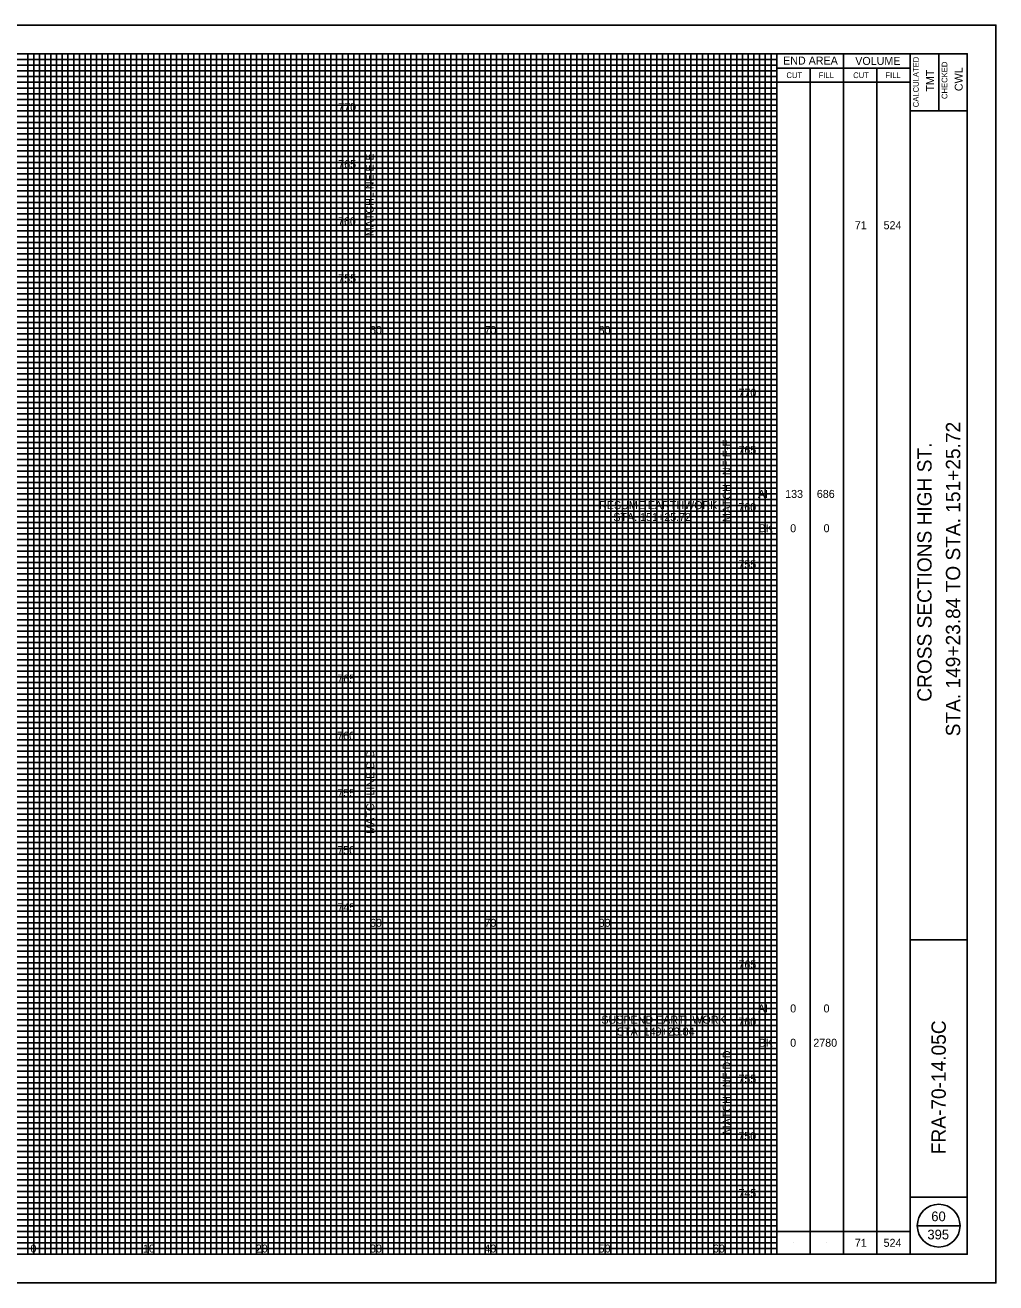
# Model space of a CAD drawing. Extents: x -10 to 160, y -2 to 568.
# Drawn here: x 75.1 to 160, y 227.5 to 337.5 of the extents above; entities that cross this region are included whole.
import ezdxf

# ---------------------------------------------------------------- set-up
doc = ezdxf.new("R2010")
doc.units = 0
for name, color, linetype in [('DR_P_Text', 7, 'Continuous'), ('SV_X_Text_Comment', 7, 'Continuous'), ('SV_X_Text_Elevation', 7, 'Continuous'), ('XS_P_Annotation', 7, 'Continuous'), ('XS_P_Finished_Grade', 7, 'Continuous'), ('XS_P_Subgrade', 7, 'Continuous'), ('XS_P_Text_MarkedPoint', 7, 'Continuous')]:
    doc.layers.add(name, color=color, linetype=linetype)

msp = doc.modelspace()

# ---------------------------------------------------------------- linework, layer by layer
at = {"layer": 'SV_X_Text_Comment'}
msp.add_lwpolyline([(-10, 227.5), (160, 227.5), (160, 337.5), (-10, 337.5)], close=True, dxfattribs=at)
at = {"layer": 'SV_X_Text_Elevation'}
for p, q in [((5.83, 334.5), (140.83, 334.5)), ((75.33, 230), (75.33, 335)), ((76.33, 230), (76.33, 335)), ((76.83, 230), (76.83, 335)), ((77.33, 230), (77.33, 335)), ((77.83, 230), (77.83, 335)), ((78.33, 230), (78.33, 335)), ((78.83, 230), (78.83, 335)), ((79.33, 230), (79.33, 335)), ((79.83, 230), (79.83, 335)), ((80.33, 230), (80.33, 335)), ((81.33, 230), (81.33, 335)), ((81.83, 230), (81.83, 335)), ((82.33, 230), (82.33, 335)), ((82.83, 230), (82.83, 335)), ((83.33, 230), (83.33, 335)), ((83.83, 230), (83.83, 335)), ((84.33, 230), (84.33, 335)), ((84.83, 230), (84.83, 335)), ((85.33, 230), (85.33, 335)), ((86.33, 230), (86.33, 335)), ((86.83, 230), (86.83, 335)), ((87.33, 230), (87.33, 335)), ((87.83, 230), (87.83, 335)), ((88.33, 230), (88.33, 335)), ((88.83, 230), (88.83, 335)), ((89.33, 230), (89.33, 335)), ((89.83, 230), (89.83, 335)), ((90.33, 230), (90.33, 335)), ((91.33, 230), (91.33, 335)), ((91.83, 230), (91.83, 335)), ((92.33, 230), (92.33, 335)), ((92.83, 230), (92.83, 335)), ((93.33, 230), (93.33, 335)), ((93.83, 230), (93.83, 335)), ((94.33, 230), (94.33, 335)), ((94.83, 230), (94.83, 335)), ((95.33, 230), (95.33, 335)), ((96.33, 230), (96.33, 335)), ((96.83, 230), (96.83, 335)), ((97.33, 230), (97.33, 335)), ((97.83, 230), (97.83, 335)), ((98.33, 230), (98.33, 335)), ((98.83, 230), (98.83, 335)), ((99.33, 230), (99.33, 335)), ((99.83, 230), (99.83, 335)), ((100.33, 230), (100.33, 335)), ((101.33, 230), (101.33, 335)), ((101.83, 230), (101.83, 335)), ((102.33, 230), (102.33, 335)), ((102.83, 230), (102.83, 335)), ((103.33, 230), (103.33, 335)), ((103.83, 230), (103.83, 335)), ((104.33, 230), (104.33, 335)), ((104.83, 230), (104.83, 335)), ((105.33, 230), (105.33, 335)), ((106.33, 230), (106.33, 335)), ((106.83, 230), (106.83, 335)), ((107.33, 230), (107.33, 335)), ((107.83, 230), (107.83, 335)), ((108.33, 230), (108.33, 335)), ((108.83, 230), (108.83, 335)), ((109.33, 230), (109.33, 335)), ((109.83, 230), (109.83, 335)), ((110.33, 230), (110.33, 335)), ((111.33, 230), (111.33, 335)), ((111.83, 230), (111.83, 335)), ((112.33, 230), (112.33, 335)), ((112.83, 230), (112.83, 335)), ((113.33, 230), (113.33, 335)), ((113.83, 230), (113.83, 335)), ((114.33, 230), (114.33, 335)), ((114.83, 230), (114.83, 335)), ((115.33, 230), (115.33, 335)), ((116.33, 230), (116.33, 335)), ((116.83, 230), (116.83, 335)), ((117.33, 230), (117.33, 335)), ((117.83, 230), (117.83, 335)), ((118.33, 230), (118.33, 335)), ((118.83, 230), (118.83, 335)), ((119.33, 230), (119.33, 335)), ((119.83, 230), (119.83, 335)), ((120.33, 230), (120.33, 335)), ((121.33, 230), (121.33, 335)), ((121.83, 230), (121.83, 335)), ((122.33, 230), (122.33, 335)), ((122.83, 230), (122.83, 335)), ((123.33, 230), (123.33, 335)), ((123.83, 230), (123.83, 335)), ((124.33, 230), (124.33, 335)), ((124.83, 230), (124.83, 335)), ((125.33, 230), (125.33, 335)), ((126.33, 230), (126.33, 335)), ((126.83, 230), (126.83, 335)), ((127.33, 230), (127.33, 335)), ((127.83, 230), (127.83, 335)), ((128.33, 230), (128.33, 335)), ((128.83, 230), (128.83, 335)), ((129.33, 230), (129.33, 335)), ((129.83, 230), (129.83, 335)), ((130.33, 230), (130.33, 335)), ((131.33, 230), (131.33, 335)), ((131.83, 230), (131.83, 335)), ((132.33, 230), (132.33, 335)), ((132.83, 230), (132.83, 335)), ((133.33, 230), (133.33, 335)), ((133.83, 230), (133.83, 335)), ((134.33, 230), (134.33, 335)), ((134.83, 230), (134.83, 335)), ((135.33, 230), (135.33, 335)), ((136.33, 230), (136.33, 335)), ((136.83, 230), (136.83, 335)), ((137.33, 230), (137.33, 335)), ((137.83, 230), (137.83, 335)), ((138.33, 230), (138.33, 335)), ((138.83, 230), (138.83, 335)), ((139.33, 230), (139.33, 335)), ((139.83, 230), (139.83, 335)), ((140.33, 230), (140.33, 335)), ((5.83, 334), (140.83, 334)), ((5.83, 333.5), (140.83, 333.5)), ((5.83, 333), (140.83, 333)), ((5.83, 332.5), (140.83, 332.5)), ((5.83, 332), (140.83, 332)), ((5.83, 331.5), (140.83, 331.5)), ((5.83, 331), (140.83, 331)), ((5.83, 330.5), (140.83, 330.5)), ((5.83, 329.5), (140.83, 329.5)), ((5.83, 329), (140.83, 329)), ((5.83, 328.5), (140.83, 328.5)), ((5.83, 328), (140.83, 328)), ((5.83, 327.5), (140.83, 327.5)), ((5.83, 327), (140.83, 327)), ((5.83, 326.5), (140.83, 326.5)), ((5.83, 326), (140.83, 326)), ((5.83, 325.5), (140.83, 325.5)), ((5.83, 324.5), (140.83, 324.5)), ((5.83, 324), (140.83, 324)), ((5.83, 323.5), (140.83, 323.5)), ((5.83, 323), (140.83, 323)), ((5.83, 322.5), (140.83, 322.5)), ((5.83, 322), (140.83, 322)), ((5.83, 321.5), (140.83, 321.5)), ((5.83, 321), (140.83, 321)), ((5.83, 320.5), (140.83, 320.5)), ((5.83, 319.5), (140.83, 319.5)), ((5.83, 319), (140.83, 319)), ((5.83, 318.5), (140.83, 318.5)), ((5.83, 318), (140.83, 318)), ((5.83, 317.5), (140.83, 317.5)), ((5.83, 317), (140.83, 317)), ((5.83, 316.5), (140.83, 316.5)), ((5.83, 316), (140.83, 316)), ((5.83, 315.5), (140.83, 315.5)), ((5.83, 314.5), (140.83, 314.5)), ((5.83, 314), (140.83, 314)), ((5.83, 313.5), (140.83, 313.5)), ((5.83, 313), (140.83, 313)), ((5.83, 312.5), (140.83, 312.5)), ((5.83, 312), (140.83, 312)), ((5.83, 311.5), (140.83, 311.5)), ((5.83, 311), (140.83, 311)), ((5.83, 310.5), (140.83, 310.5)), ((5.83, 309.5), (140.83, 309.5)), ((5.83, 309), (140.83, 309)), ((5.83, 308.5), (140.83, 308.5)), ((5.83, 308), (140.83, 308)), ((5.83, 307.5), (140.83, 307.5)), ((5.83, 307), (140.83, 307)), ((5.83, 306.5), (140.83, 306.5)), ((5.83, 306), (140.83, 306)), ((5.83, 305.5), (140.83, 305.5)), ((5.83, 304.5), (140.83, 304.5)), ((5.83, 304), (140.83, 304)), ((5.83, 303.5), (140.83, 303.5)), ((5.83, 303), (140.83, 303)), ((5.83, 302.5), (140.83, 302.5)), ((5.83, 302), (140.83, 302)), ((5.83, 301.5), (140.83, 301.5)), ((5.83, 301), (140.83, 301)), ((5.83, 300.5), (140.83, 300.5)), ((5.83, 299.5), (140.83, 299.5)), ((5.83, 299), (140.83, 299)), ((5.83, 298.5), (140.83, 298.5)), ((5.83, 298), (140.83, 298)), ((5.83, 297.5), (140.83, 297.5)), ((5.83, 297), (140.83, 297)), ((5.83, 296.5), (140.83, 296.5)), ((5.83, 296), (140.83, 296)), ((5.83, 295.5), (140.83, 295.5)), ((5.83, 294.5), (140.83, 294.5)), ((5.83, 294), (140.83, 294)), ((5.83, 293.5), (140.83, 293.5)), ((5.83, 293), (140.83, 293)), ((5.83, 292.5), (140.83, 292.5)), ((5.83, 292), (140.83, 292)), ((5.83, 291.5), (140.83, 291.5)), ((5.83, 291), (140.83, 291)), ((5.83, 290.5), (140.83, 290.5)), ((5.83, 289.5), (140.83, 289.5)), ((5.83, 289), (140.83, 289)), ((5.83, 288.5), (140.83, 288.5)), ((5.83, 288), (140.83, 288)), ((5.83, 287.5), (140.83, 287.5)), ((5.83, 287), (140.83, 287)), ((5.83, 286.5), (140.83, 286.5)), ((5.83, 286), (140.83, 286)), ((5.83, 285.5), (140.83, 285.5)), ((5.83, 284.5), (140.83, 284.5)), ((5.83, 284), (140.83, 284)), ((5.83, 283.5), (140.83, 283.5)), ((5.83, 283), (140.83, 283)), ((5.83, 282.5), (140.83, 282.5)), ((5.83, 282), (140.83, 282)), ((5.83, 281.5), (140.83, 281.5)), ((5.83, 281), (140.83, 281)), ((5.83, 280.5), (140.83, 280.5)), ((5.83, 279.5), (140.83, 279.5)), ((5.83, 279), (140.83, 279)), ((5.83, 278.5), (140.83, 278.5)), ((5.83, 278), (140.83, 278)), ((5.83, 277.5), (140.83, 277.5)), ((5.83, 277), (140.83, 277)), ((5.83, 276.5), (140.83, 276.5)), ((5.83, 276), (140.83, 276)), ((5.83, 275.5), (140.83, 275.5)), ((5.83, 274.5), (140.83, 274.5)), ((5.83, 274), (140.83, 274)), ((5.83, 273.5), (140.83, 273.5)), ((5.83, 273), (140.83, 273)), ((5.83, 272.5), (140.83, 272.5)), ((5.83, 272), (140.83, 272)), ((5.83, 271.5), (140.83, 271.5)), ((5.83, 271), (140.83, 271)), ((5.83, 270.5), (140.83, 270.5)), ((5.83, 269.5), (140.83, 269.5)), ((5.83, 269), (140.83, 269)), ((5.83, 268.5), (140.83, 268.5)), ((5.83, 268), (140.83, 268)), ((5.83, 267.5), (140.83, 267.5)), ((5.83, 267), (140.83, 267)), ((5.83, 266.5), (140.83, 266.5)), ((5.83, 266), (140.83, 266)), ((5.83, 265.5), (140.83, 265.5)), ((5.83, 264.5), (140.83, 264.5)), ((5.83, 264), (140.83, 264)), ((5.83, 263.5), (140.83, 263.5)), ((5.83, 263), (140.83, 263)), ((5.83, 262.5), (140.83, 262.5)), ((5.83, 262), (140.83, 262)), ((5.83, 261.5), (140.83, 261.5)), ((5.83, 261), (140.83, 261)), ((5.83, 260.5), (140.83, 260.5)), ((5.83, 259.5), (140.83, 259.5)), ((5.83, 259), (140.83, 259)), ((5.83, 258.5), (140.83, 258.5)), ((5.83, 258), (140.83, 258)), ((5.83, 257.5), (140.83, 257.5)), ((5.83, 257), (140.83, 257)), ((5.83, 256.5), (140.83, 256.5)), ((5.83, 256), (140.83, 256)), ((5.83, 255.5), (140.83, 255.5)), ((5.83, 254.5), (140.83, 254.5)), ((5.83, 254), (140.83, 254)), ((5.83, 253.5), (140.83, 253.5)), ((5.83, 253), (140.83, 253)), ((5.83, 252.5), (140.83, 252.5)), ((5.83, 252), (140.83, 252)), ((5.83, 251.5), (140.83, 251.5)), ((5.83, 251), (140.83, 251)), ((5.83, 250.5), (140.83, 250.5)), ((5.83, 249.5), (140.83, 249.5)), ((5.83, 249), (140.83, 249)), ((5.83, 248.5), (140.83, 248.5)), ((5.83, 248), (140.83, 248)), ((5.83, 247.5), (140.83, 247.5)), ((5.83, 247), (140.83, 247)), ((5.83, 246.5), (140.83, 246.5)), ((5.83, 246), (140.83, 246)), ((5.83, 245.5), (140.83, 245.5)), ((5.83, 244.5), (140.83, 244.5)), ((5.83, 244), (140.83, 244)), ((5.83, 243.5), (140.83, 243.5)), ((5.83, 243), (140.83, 243)), ((5.83, 242.5), (140.83, 242.5)), ((5.83, 242), (140.83, 242)), ((5.83, 241.5), (140.83, 241.5)), ((5.83, 241), (140.83, 241)), ((5.83, 240.5), (140.83, 240.5)), ((5.83, 239.5), (140.83, 239.5)), ((5.83, 239), (140.83, 239)), ((5.83, 238.5), (140.83, 238.5)), ((5.83, 238), (140.83, 238)), ((5.83, 237.5), (140.83, 237.5)), ((5.83, 237), (140.83, 237)), ((5.83, 236.5), (140.83, 236.5)), ((5.83, 236), (140.83, 236)), ((5.83, 235.5), (140.83, 235.5)), ((5.83, 234.5), (140.83, 234.5)), ((5.83, 234), (140.83, 234)), ((5.83, 233.5), (140.83, 233.5)), ((5.83, 233), (140.83, 233)), ((5.83, 232.5), (140.83, 232.5)), ((5.83, 232), (140.83, 232)), ((5.83, 231.5), (140.83, 231.5)), ((5.83, 231), (140.83, 231)), ((5.83, 230.5), (140.83, 230.5))]:
    msp.add_line(p, q, dxfattribs=at)
at = {"layer": 'XS_P_Annotation'}
for p, q in [((152.5, 230), (152.5, 335)), ((155, 335), (155, 330)), ((152.5, 330), (157.5, 330)), ((152.5, 257.5), (157.5, 257.5)), ((152.5, 235), (157.5, 235))]:
    msp.add_line(p, q, dxfattribs=at)
msp.add_lwpolyline([(0, 335), (157.5, 335), (157.5, 230), (0, 230)], close=True, dxfattribs=at)
at = {"layer": 'XS_P_Finished_Grade'}
for p, q in [((140.83, 230), (140.83, 335)), ((146.67, 230), (146.67, 335)), ((140.83, 333.75), (152.5, 333.75)), ((143.75, 230), (143.75, 333.75)), ((149.58, 230), (149.58, 333.75)), ((140.83, 332.5), (152.5, 332.5)), ((153.12, 232.5), (156.88, 232.5)), ((140.83, 232), (152.5, 232)), ((142.29, 231), (142.29, 231)), ((145.21, 231), (145.21, 231)), ((148.12, 231), (148.12, 231)), ((151.04, 231), (151.04, 231))]:
    msp.add_line(p, q, dxfattribs=at)
msp.add_circle((155, 232.5), 1.87, dxfattribs=at)
at = {"layer": 'XS_P_Subgrade'}
for p, q in [((105.83, 313.17), (105.83, 332.32)), ((135.83, 288.17), (135.83, 307.32)), ((105.83, 260.26), (105.83, 283.35)), ((135.83, 233.97), (135.83, 257.06))]:
    msp.add_line(p, q, dxfattribs=at)
at = {"layer": 'XS_P_Text_MarkedPoint'}
for p, q in [((75.83, 230), (75.83, 335)), ((80.83, 230), (80.83, 335)), ((85.83, 230), (85.83, 335)), ((90.83, 230), (90.83, 335)), ((95.83, 230), (95.83, 335)), ((100.83, 230), (100.83, 335)), ((105.83, 230), (105.83, 335)), ((110.83, 230), (110.83, 335)), ((115.83, 230), (115.83, 335)), ((120.83, 230), (120.83, 335)), ((125.83, 230), (125.83, 335)), ((130.83, 230), (130.83, 335)), ((135.83, 230), (135.83, 335)), ((5.83, 330), (140.83, 330)), ((5.83, 325), (140.83, 325)), ((5.83, 320), (140.83, 320)), ((5.83, 315), (140.83, 315)), ((5.83, 310), (140.83, 310)), ((5.83, 305), (140.83, 305)), ((5.83, 300), (140.83, 300)), ((5.83, 295), (140.83, 295)), ((5.83, 290), (140.83, 290)), ((5.83, 285), (140.83, 285)), ((5.83, 280), (140.83, 280)), ((5.83, 275), (140.83, 275)), ((5.83, 270), (140.83, 270)), ((5.83, 265), (140.83, 265)), ((5.83, 260), (140.83, 260)), ((5.83, 255), (140.83, 255)), ((5.83, 250), (140.83, 250)), ((5.83, 245), (140.83, 245)), ((5.83, 240), (140.83, 240)), ((5.83, 235), (140.83, 235))]:
    msp.add_line(p, q, dxfattribs=at)

# ---------------------------------------------------------------- texts
at = {"layer": 'DR_P_Text'}
for s, p in [('770', (102.47, 330)), ('765', (102.47, 325)), ('760', (102.45, 320)), ('71', (147.66, 319.65)), ('524', (150.18, 319.65)), ('755', (102.47, 315)), ('60', (105.25, 310.48)), ('70', (115.26, 310.48)), ('80', (125.25, 310.48)), ('770', (137.48, 305)), ('765', (137.48, 300)), ('AH', (139.19, 296.15)), ('133', (141.57, 296.15)), ('686', (144.34, 296.15)), ('760', (137.47, 295)), ('BK', (139.26, 293.15)), ('0', (142.01, 293.15)), ('0', (144.93, 293.15)), ('755', (137.48, 290)), ('765', (102.39, 280)), ('760', (102.38, 275)), ('755', (102.4, 270)), ('750', (102.39, 265)), ('745', (102.4, 260)), ('60', (105.25, 258.64)), ('70', (115.26, 258.64)), ('80', (125.25, 258.64)), ('765', (137.48, 255)), ('AH', (139.19, 251.15)), ('0', (142.01, 251.15)), ('0', (144.93, 251.15)), ('760', (137.47, 250)), ('BK', (139.26, 248.15)), ('0', (142.01, 248.15)), ('2780', (144.03, 248.15)), ('755', (137.48, 245)), ('750', (137.47, 240)), ('745', (137.48, 235)), ('71', (147.66, 230.65)), ('524', (150.18, 230.65)), ('0', (75.55, 230.15)), ('0', (75.55, 230.15)), ('10', (85.39, 230.15)), ('20', (95.26, 230.15)), ('30', (105.25, 230.15)), ('40', (115.25, 230.15)), ('50', (125.25, 230.15)), ('60', (135.25, 230.15))]:
    msp.add_text(s, height=0.7, dxfattribs=at).set_placement(p)
at = {"layer": 'XS_P_Finished_Grade'}
for s, height, p in [('END AREA', 0.7, (141.39, 334.05)), ('VOLUME', 0.7, (147.7, 334.02)), ('CUT', 0.5, (141.68, 332.87)), ('FILL', 0.5, (144.5, 332.87)), ('CUT', 0.5, (147.52, 332.87)), ('FILL', 0.5, (150.34, 332.87)), ('60', 0.85, (154.35, 232.89)), ('395', 0.85, (154.01, 231.3))]:
    msp.add_text(s, height=height, dxfattribs=at).set_placement(p)
for s, height, p in [('CALCULATED', 0.5, (153.26, 330.32)), ('TMT', 0.7, (154.6, 331.69)), ('CHECKED', 0.5, (155.76, 331.04)), ('CWL', 0.7, (157.1, 331.73)), ('STA. 149+23.84 TO STA. 151+25.72', 1.25, (156.88, 275.3)), ('CROSS SECTIONS HIGH ST.', 1.25, (154.38, 278.33)), ('FRA-70-14.05C', 1.25, (155.62, 238.75))]:
    msp.add_text(s, height=height, rotation=90, dxfattribs=at).set_placement(p)
at = {"layer": 'XS_P_Subgrade'}
for s, p in [('MATCHLINE E-E', (105.57, 319.04)), ('MATCHLINE E-E', (136.81, 294.04)), ('MATCHLINE D-D', (105.62, 266.78)), ('MATCHLINE D-D', (136.81, 240.49))]:
    msp.add_text(s, height=0.7, rotation=90, dxfattribs=at).set_placement(p)
for s, p in [('RESUME EARTHWORK', (125.29, 295.17)), ('STA. 151+25.72', (126.54, 294.13)), ('SUSPEND EARTHWORK', (125.49, 250.17)), ('STA. 149+23.84', (126.85, 249.13))]:
    msp.add_text(s, height=0.7, dxfattribs=at).set_placement(p)

doc.saveas('drawing.dxf')
